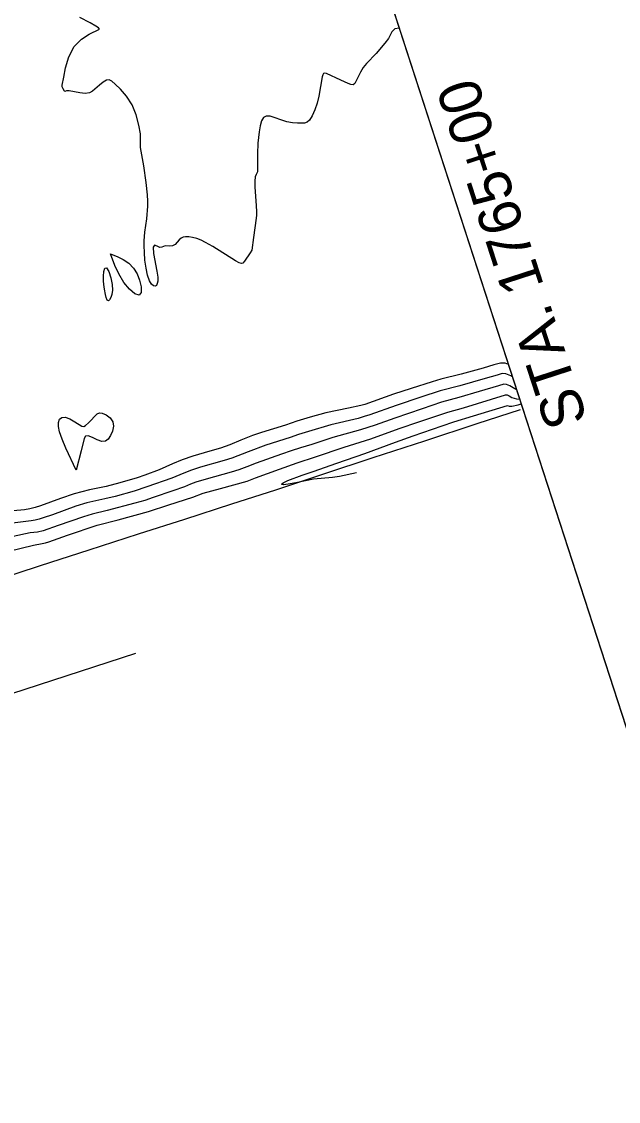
# Model space of a CAD drawing. Extents: x -468548933 to 3387700, y -306089263 to 1207014.
# Drawn here: x 1841391 to 1842053, y 536784 to 537981 of the extents above; entities that cross this region are included whole.
import ezdxf

# ---------------------------------------------------------------- set-up
doc = ezdxf.new("R2010")
doc.units = 0
for name, color, linetype in [('DT_X_Contour_Minor', 7, 'Continuous'), ('DT_X_Terrain_Ground_Line', 7, 'Continuous'), ('Level 14', 7, 'Continuous'), ('Level 40', 7, 'Continuous'), ('SC_Scratch1', 7, 'Continuous')]:
    doc.layers.add(name, color=color, linetype=linetype)

msp = doc.modelspace()

# ---------------------------------------------------------------- linework, layer by layer
at = {"layer": 'DT_X_Contour_Minor'}
for points in [[(1841652.5, 537814.7), (1841651, 537811.9), (1841650.1, 537809), (1841649.5, 537804.4), (1841649.5, 537797.8), (1841650.5, 537782.5), (1841651.4, 537770.9), (1841651.5, 537766.7), (1841651.2, 537763.3), (1841647.9, 537741.8), (1841646.3, 537727.9), (1841644.5, 537724.9), (1841638.1, 537715.5), (1841636.4, 537713.5), (1841634.6, 537712.9), (1841632.1, 537713.7), (1841628.2, 537715.9), (1841602.9, 537731.8), (1841594.7, 537736.5), (1841589.9, 537738.8), (1841585.1, 537740.7), (1841580.5, 537741.9), (1841576.3, 537742.5), (1841572.8, 537742.5), (1841570.1, 537742.1), (1841567.8, 537741), (1841565.7, 537739.2), (1841561.1, 537734.2), (1841558.4, 537732.5), (1841555.4, 537732.3), (1841550, 537732.8), (1841546.5, 537731), (1841544.3, 537730.9), (1841541.2, 537732.4), (1841538.2, 537733.4), (1841536.6, 537731.2), (1841537.2, 537724.1), (1841541, 537704.7), (1841541.9, 537697.9), (1841541.8, 537693.6), (1841541.2, 537690.8), (1841540.3, 537688.8), (1841539, 537687.8), (1841537.3, 537688.2), (1841535.1, 537690.1), (1841532.7, 537694), (1841530.6, 537700), (1841528.9, 537707.9), (1841527.7, 537716.8), (1841527.1, 537725.3), (1841526.8, 537732.5), (1841526.9, 537738.3), (1841527.7, 537747.8), (1841529.6, 537762.6), (1841530.7, 537776.7), (1841530.7, 537782), (1841530.4, 537789), (1841529, 537802.8), (1841526.5, 537821.3), (1841522.8, 537841.8), (1841522.6, 537857), (1841521, 537866.6), (1841518, 537877.9), (1841513.4, 537889.1), (1841507.2, 537898.7), (1841500.6, 537906.4), (1841494.8, 537911.9), (1841490.9, 537915.4), (1841488, 537916.8), (1841485.1, 537916.2), (1841481.3, 537914), (1841477.1, 537910.7), (1841469.5, 537904.3), (1841466, 537902.3), (1841461.4, 537901.6), (1841455.4, 537902.3), (1841443.7, 537904.6), (1841440.8, 537904.6), (1841438.9, 537903.8), (1841438.3, 537904.3), (1841436.8, 537906.8), (1841436, 537908.8), (1841435.8, 537909.7), (1841435.9, 537910.8), (1841437.5, 537919.7), (1841439.6, 537929.9), (1841443.2, 537942.2), (1841449, 537953.6), (1841457.1, 537961.9), (1841465.8, 537967.4), (1841477.3, 537972.8), (1841476, 537974.3), (1841473.2, 537976.3), (1841466.8, 537980.1), (1841455.6, 537985.7)], [(1841810, 537973.7), (1841809.7, 537973.9), (1841804.9, 537973.4), (1841801.6, 537969.8), (1841797.7, 537962.4), (1841793.7, 537957.3), (1841784.1, 537945.8), (1841773.5, 537934.9), (1841769.9, 537930.3), (1841766.7, 537925.2), (1841760.5, 537912.7), (1841758.5, 537911.3), (1841756.1, 537911.4), (1841753.1, 537912.5), (1841745, 537916.2), (1841729.2, 537923.9), (1841727, 537924.2), (1841725.7, 537923.6), (1841724.8, 537922.1), (1841724.2, 537919.9), (1841720.6, 537898.6), (1841718.6, 537890.9), (1841716, 537883.4), (1841713.1, 537876.9), (1841710.2, 537872.1), (1841707.6, 537869.6), (1841704.8, 537868.7), (1841696.9, 537868.7), (1841691.4, 537869.1), (1841685.1, 537870.3), (1841678.5, 537872.3), (1841672, 537874.6), (1841666.4, 537876.3), (1841662.1, 537876.4), (1841659.1, 537874.8), (1841656.9, 537871.3), (1841655.3, 537865.8), (1841654.2, 537859.1), (1841653, 537846.3), (1841652.5, 537834.8), (1841652.5, 537814.7)], [(1841489.3, 537723.6), (1841497.7, 537720.3), (1841503.6, 537717.4), (1841509.7, 537713.3), (1841514.8, 537708), (1841518.9, 537701.6), (1841521.8, 537694.5), (1841523.5, 537687.1), (1841523.4, 537681), (1841521.2, 537678), (1841516.6, 537679.3), (1841510.4, 537684.4), (1841504.1, 537692.1), (1841498.7, 537701.5), (1841494.4, 537710.7), (1841489.3, 537723.6)], [(1841482.9, 537684.5), (1841482, 537689.8), (1841481.5, 537694), (1841481.5, 537699), (1841482, 537704.1), (1841483.2, 537707.8), (1841485.1, 537708.2), (1841487.5, 537704.1), (1841489.8, 537697.2), (1841491.4, 537689.7), (1841491.7, 537683.5), (1841490.9, 537678.7), (1841489.7, 537675.2), (1841488.4, 537672.8), (1841487.1, 537671.8), (1841485.8, 537672.5), (1841484.8, 537675.2), (1841483.9, 537678.8), (1841482.9, 537684.5)], [(1841931, 537600.9), (1841927.3, 537602.4), (1841922.1, 537602.6), (1841914.6, 537600.5), (1841903, 537597.1), (1841878.4, 537590.4), (1841855.8, 537584.8), (1841846.1, 537581.9), (1841822.9, 537574.4), (1841803.4, 537568.1), (1841771.5, 537556.8), (1841767.2, 537555.5), (1841753.5, 537552.6), (1841728.4, 537547.5), (1841710.8, 537542.8), (1841696.2, 537538.2), (1841683.6, 537533.8), (1841670.1, 537529.7), (1841656.9, 537525.7), (1841646.9, 537522.2), (1841634.1, 537517.1), (1841621.8, 537512.1), (1841611.6, 537508.4), (1841599.7, 537504.9), (1841580.9, 537499.4), (1841569.1, 537495.4), (1841558.1, 537490.8), (1841543.5, 537484.4), (1841527.5, 537478.4), (1841518.9, 537475.5), (1841499.8, 537469.8), (1841484.5, 537465.8), (1841466.2, 537462), (1841457.5, 537460), (1841449.3, 537457.6), (1841434.1, 537452.4), (1841411.9, 537444.2), (1841405.9, 537442.4), (1841400.1, 537440.9), (1841394.1, 537439.9), (1841381.3, 537438.6)], [(1841935.4, 537587.3), (1841933.5, 537588.5), (1841927.9, 537590.7), (1841924, 537590.9), (1841918.2, 537589.2), (1841905.2, 537585.5), (1841877.1, 537577.3), (1841855, 537571.7), (1841833.7, 537564.7), (1841806.5, 537555.7), (1841777.3, 537545.3), (1841770.9, 537543.2), (1841764.1, 537541.3), (1841733.8, 537534.1), (1841709.2, 537526.9), (1841698.1, 537523.4), (1841688.6, 537520.1), (1841661.7, 537511.4), (1841642.2, 537504.3), (1841624.1, 537497), (1841615.7, 537494.4), (1841589.3, 537487), (1841579.3, 537483.9), (1841570.9, 537480.7), (1841557.5, 537475), (1841529.8, 537465.2), (1841515.7, 537460.7), (1841494.6, 537454.8), (1841483.1, 537452), (1841463.3, 537447.6), (1841450.9, 537443.8), (1841425.1, 537434.5), (1841414.9, 537430.9), (1841410.4, 537429.5), (1841405.9, 537428.4), (1841401.3, 537427.6), (1841380.9, 537424.9)], [(1841940, 537573.1), (1841937.9, 537574.2), (1841932.5, 537577.5), (1841928.6, 537579), (1841925.8, 537579.1), (1841919.8, 537577.4), (1841898.5, 537571), (1841875.8, 537564.3), (1841856.7, 537559.2), (1841835, 537551.9), (1841804.7, 537541.6), (1841783.1, 537533.8), (1841766.6, 537528.4), (1841736, 537520), (1841712.9, 537512.5), (1841700.1, 537508.6), (1841690, 537505.2), (1841679.3, 537501.7), (1841651.1, 537491.5), (1841640.7, 537487.6), (1841631.8, 537484.1), (1841623.4, 537481.6), (1841595.4, 537473.9), (1841584, 537470.4), (1841578.2, 537468.3), (1841571.4, 537465.5), (1841558.7, 537461), (1841536.9, 537453.7), (1841527.4, 537450.4), (1841516.3, 537447.2), (1841485.8, 537439.1), (1841469, 537435.2), (1841459.5, 537432.2), (1841431.5, 537422.4), (1841414.8, 537416.6), (1841408.5, 537415.2), (1841400.5, 537414.2), (1841395, 537413.3), (1841369.5, 537407.7)], [(1841376.7, 537393.9), (1841404.2, 537400.8), (1841413.6, 537402.6), (1841417.5, 537403.2), (1841421, 537404.2), (1841441.9, 537411.6), (1841474.8, 537422.8), (1841497.8, 537428.6), (1841531.7, 537437.9), (1841554.1, 537445.3), (1841580.6, 537453.9), (1841592.3, 537458.2), (1841611.5, 537463.4), (1841641.1, 537471.6), (1841650.3, 537475.2), (1841676.8, 537485), (1841696.6, 537492), (1841716.8, 537498.5), (1841748.5, 537509.3), (1841778.4, 537518.7), (1841809.8, 537529.9), (1841831.5, 537537.4), (1841863.6, 537548.3), (1841881, 537553.1), (1841912.1, 537562.7), (1841927.7, 537567.3), (1841929.3, 537567.3), (1841931.5, 537566.4), (1841934.8, 537564.6), (1841939.8, 537562.8), (1841943.4, 537562.6)], [(1841762.2, 537480.9), (1841743.6, 537476.9), (1841735.8, 537475.7), (1841714.8, 537473.7), (1841695.1, 537469.8), (1841686.6, 537468.2), (1841681.2, 537467.7), (1841679.3, 537468.2), (1841681.1, 537469.9), (1841686.2, 537472.3), (1841702, 537478.3), (1841714.2, 537482.5), (1841740.4, 537491.7), (1841771.5, 537502.5), (1841805.5, 537514.9), (1841825, 537521.8), (1841857.5, 537533), (1841870.4, 537537.3), (1841892.2, 537544), (1841930, 537555.5), (1841931.7, 537554.9), (1841934.8, 537555), (1841941.6, 537556.4), (1841945.1, 537557.4)], [(1841451.5, 537483.9), (1841440, 537508.4), (1841435.8, 537518.3), (1841433, 537526.2), (1841431.7, 537532.1), (1841431.8, 537536.7), (1841432.9, 537540.3), (1841435.4, 537542.4), (1841439.3, 537542.6), (1841444.4, 537540.7), (1841450, 537537.5), (1841457.7, 537532.6), (1841459.8, 537532.2), (1841461.9, 537533.5), (1841465, 537536.4), (1841474.5, 537546.3), (1841477.1, 537547.4), (1841480.3, 537547.1), (1841484.6, 537545.2), (1841489, 537541.9), (1841492, 537537.6), (1841492.7, 537532.5), (1841491.6, 537527.2), (1841489.5, 537522.3), (1841487, 537518.4), (1841483.9, 537516), (1841479.9, 537515.7), (1841474.7, 537517.4), (1841469.3, 537520.1), (1841464.8, 537521.9), (1841461.9, 537521.6), (1841460.2, 537518.8), (1841456.8, 537505.3), (1841451.5, 537483.9)]]:
    msp.add_lwpolyline(points, dxfattribs=at)
at = {"layer": 'DT_X_Terrain_Ground_Line'}
msp.add_line((1842189.4, 536805.1), (1841581.8, 538676.6), dxfattribs=at)
at = {"layer": 'Level 14'}
msp.add_lwpolyline([(1841360.6, 537361.5), (1841411.8, 537378), (1841465.9, 537395.5), (1841520.5, 537413.1), (1841571.8, 537429.7), (1841624.1, 537446.5), (1841672.7, 537462.1), (1841726, 537479.8), (1841780.9, 537497.8), (1841838.2, 537516.5), (1841896.1, 537535.5), (1841944.4, 537551.3)], dxfattribs=at)
at = {"layer": 'Level 40'}
msp.add_line((1840775.2, 537040.1), (1841517.7, 537281.1), dxfattribs=at)
at = {"layer": 'SC_Scratch1'}
msp.add_lwpolyline([(1834448.4, 536360.5), (1835055.8, 534489.4), (1836664.2, 534206.2), (1839225.8, 534394.2), (1842361.7, 536308.3), (1842189.4, 536805.1), (1841581.8, 538676.6), (1840313.7, 539042.5), (1837357.7, 538260.2), (1834781, 538194.3), (1834403.1, 536496.4)], close=True, dxfattribs=at)

# ---------------------------------------------------------------- texts
at = {"layer": 'DT_X_Terrain_Ground_Line'}
msp.add_text('MATCH LINE                  STA. 1765+00', height=46.8, rotation=107.9864, dxfattribs=at).set_placement((1842232.6, 536881.1))

doc.saveas('drawing.dxf')
